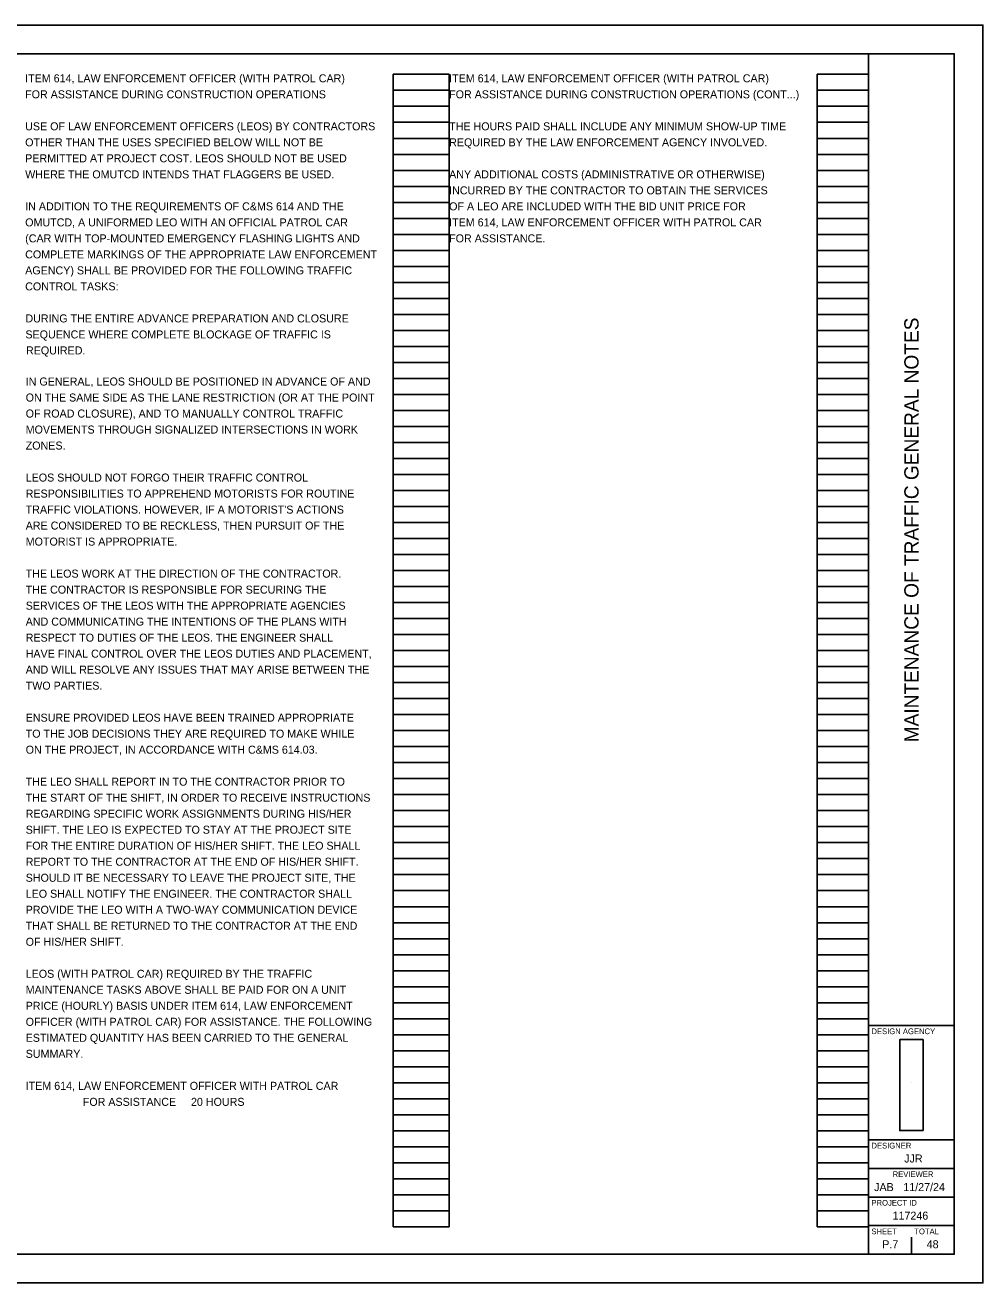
# Model space of a CAD drawing. Extents: x -1.4 to 32.6, y -1 to 21.
# Drawn here: x 15.82 to 32.57, y -0.97 to 21.03 of the extents above; entities that cross this region are included whole.
import ezdxf

# ---------------------------------------------------------------- set-up
doc = ezdxf.new("R2010")
doc.units = 0
for name, color, linetype in [('SH_Border', 7, 'Continuous'), ('SH_Cut_Line', 7, 'Continuous'), ('SH_Data', 7, 'Continuous'), ('SH_Text', 7, 'Continuous')]:
    doc.layers.add(name, color=color, linetype=linetype)

msp = doc.modelspace()

# ---------------------------------------------------------------- linework, layer by layer
at = {"layer": 'SH_Border'}
for p, q in [((30.575, -0.468), (30.575, 20.532)), ((30.575, 3.532), (32.075, 3.532)), ((30.575, 1.532), (32.075, 1.532)), ((30.575, 1.032), (32.075, 1.032)), ((30.575, 0.532), (32.075, 0.532)), ((30.575, 0.032), (32.075, 0.032))]:
    msp.add_line(p, q, dxfattribs=at)
msp.add_lwpolyline([(0.075, 20.532), (32.075, 20.532), (32.075, -0.468), (0.075, -0.468)], close=True, dxfattribs=at)
at = {"layer": 'SH_Cut_Line'}
msp.add_lwpolyline([(-1.425, -0.968), (32.575, -0.968), (32.575, 21.032), (-1.425, 21.032)], close=True, dxfattribs=at)
at = {"layer": 'SH_Data'}
for p, q in [((22.255, 0.012), (22.255, 20.172)), ((22.255, 20.172), (23.235, 20.172)), ((23.235, 0.012), (23.235, 20.172)), ((29.675, 0.012), (29.675, 20.172)), ((29.675, 20.172), (30.575, 20.172)), ((30.575, 0.012), (30.575, 20.172)), ((22.255, 19.892), (23.235, 19.892)), ((29.675, 19.892), (30.575, 19.892)), ((22.255, 19.612), (23.235, 19.612)), ((29.675, 19.612), (30.575, 19.612)), ((22.255, 19.332), (23.235, 19.332)), ((29.675, 19.332), (30.575, 19.332)), ((22.255, 19.052), (23.235, 19.052)), ((29.675, 19.052), (30.575, 19.052)), ((22.255, 18.772), (23.235, 18.772)), ((29.675, 18.772), (30.575, 18.772)), ((22.255, 18.492), (23.235, 18.492)), ((29.675, 18.492), (30.575, 18.492)), ((22.255, 18.212), (23.235, 18.212)), ((29.675, 18.212), (30.575, 18.212)), ((22.255, 17.932), (23.235, 17.932)), ((29.675, 17.932), (30.575, 17.932)), ((22.255, 17.652), (23.235, 17.652)), ((29.675, 17.652), (30.575, 17.652)), ((22.255, 17.372), (23.235, 17.372)), ((29.675, 17.372), (30.575, 17.372)), ((22.255, 17.092), (23.235, 17.092)), ((29.675, 17.092), (30.575, 17.092)), ((22.255, 16.812), (23.235, 16.812)), ((29.675, 16.812), (30.575, 16.812)), ((22.255, 16.532), (23.235, 16.532)), ((29.675, 16.532), (30.575, 16.532)), ((22.255, 16.252), (23.235, 16.252)), ((29.675, 16.252), (30.575, 16.252)), ((22.255, 15.972), (23.235, 15.972)), ((29.675, 15.972), (30.575, 15.972)), ((22.255, 15.692), (23.235, 15.692)), ((29.675, 15.692), (30.575, 15.692)), ((22.255, 15.412), (23.235, 15.412)), ((29.675, 15.412), (30.575, 15.412)), ((22.255, 15.132), (23.235, 15.132)), ((29.675, 15.132), (30.575, 15.132)), ((22.255, 14.852), (23.235, 14.852)), ((29.675, 14.852), (30.575, 14.852)), ((22.255, 14.572), (23.235, 14.572)), ((29.675, 14.572), (30.575, 14.572)), ((22.255, 14.292), (23.235, 14.292)), ((29.675, 14.292), (30.575, 14.292)), ((22.255, 14.012), (23.235, 14.012)), ((29.675, 14.012), (30.575, 14.012)), ((22.255, 13.732), (23.235, 13.732)), ((29.675, 13.732), (30.575, 13.732)), ((22.255, 13.452), (23.235, 13.452)), ((29.675, 13.452), (30.575, 13.452)), ((22.255, 13.172), (23.235, 13.172)), ((29.675, 13.172), (30.575, 13.172)), ((22.255, 12.892), (23.235, 12.892)), ((29.675, 12.892), (30.575, 12.892)), ((22.255, 12.612), (23.235, 12.612)), ((29.675, 12.612), (30.575, 12.612)), ((22.255, 12.332), (23.235, 12.332)), ((29.675, 12.332), (30.575, 12.332)), ((22.255, 12.052), (23.235, 12.052)), ((29.675, 12.052), (30.575, 12.052)), ((22.255, 11.772), (23.235, 11.772)), ((29.675, 11.772), (30.575, 11.772)), ((22.255, 11.492), (23.235, 11.492)), ((29.675, 11.492), (30.575, 11.492)), ((22.255, 11.212), (23.235, 11.212)), ((29.675, 11.212), (30.575, 11.212)), ((22.255, 10.932), (23.235, 10.932)), ((29.675, 10.932), (30.575, 10.932)), ((22.255, 10.652), (23.235, 10.652)), ((29.675, 10.652), (30.575, 10.652)), ((22.255, 10.372), (23.235, 10.372)), ((29.675, 10.372), (30.575, 10.372)), ((22.255, 10.092), (23.235, 10.092)), ((29.675, 10.092), (30.575, 10.092)), ((22.255, 9.812), (23.235, 9.812)), ((29.675, 9.812), (30.575, 9.812)), ((22.255, 9.532), (23.235, 9.532)), ((29.675, 9.532), (30.575, 9.532)), ((22.255, 9.252), (23.235, 9.252)), ((29.675, 9.252), (30.575, 9.252)), ((22.255, 8.972), (23.235, 8.972)), ((29.675, 8.972), (30.575, 8.972)), ((22.255, 8.692), (23.235, 8.692)), ((29.675, 8.692), (30.575, 8.692)), ((22.255, 8.412), (23.235, 8.412)), ((29.675, 8.412), (30.575, 8.412)), ((22.255, 8.132), (23.235, 8.132)), ((29.675, 8.132), (30.575, 8.132)), ((22.255, 7.852), (23.235, 7.852)), ((29.675, 7.852), (30.575, 7.852)), ((22.255, 7.572), (23.235, 7.572)), ((29.675, 7.572), (30.575, 7.572)), ((22.255, 7.292), (23.235, 7.292)), ((29.675, 7.292), (30.575, 7.292)), ((22.255, 7.012), (23.235, 7.012)), ((29.675, 7.012), (30.575, 7.012)), ((22.255, 6.732), (23.235, 6.732)), ((29.675, 6.732), (30.575, 6.732)), ((22.255, 6.452), (23.235, 6.452)), ((29.675, 6.452), (30.575, 6.452)), ((22.255, 6.172), (23.235, 6.172)), ((29.675, 6.172), (30.575, 6.172)), ((22.255, 5.892), (23.235, 5.892)), ((29.675, 5.892), (30.575, 5.892)), ((22.255, 5.612), (23.235, 5.612)), ((29.675, 5.612), (30.575, 5.612)), ((22.255, 5.332), (23.235, 5.332)), ((29.675, 5.332), (30.575, 5.332)), ((22.255, 5.052), (23.235, 5.052)), ((29.675, 5.052), (30.575, 5.052)), ((22.255, 4.772), (23.235, 4.772)), ((29.675, 4.772), (30.575, 4.772)), ((22.255, 4.492), (23.235, 4.492)), ((29.675, 4.492), (30.575, 4.492)), ((22.255, 4.212), (23.235, 4.212)), ((29.675, 4.212), (30.575, 4.212)), ((22.255, 3.932), (23.235, 3.932)), ((29.675, 3.932), (30.575, 3.932)), ((22.255, 3.652), (23.235, 3.652)), ((29.675, 3.652), (30.575, 3.652)), ((22.255, 3.372), (23.235, 3.372)), ((29.675, 3.372), (30.575, 3.372)), ((22.255, 3.092), (23.235, 3.092)), ((29.675, 3.092), (30.575, 3.092)), ((22.255, 2.812), (23.235, 2.812)), ((29.675, 2.812), (30.575, 2.812)), ((22.255, 2.532), (23.235, 2.532)), ((29.675, 2.532), (30.575, 2.532)), ((31.325, 2.532), (31.325, 2.532)), ((22.255, 2.252), (23.235, 2.252)), ((29.675, 2.252), (30.575, 2.252)), ((22.255, 1.972), (23.235, 1.972)), ((29.675, 1.972), (30.575, 1.972)), ((22.255, 1.692), (23.235, 1.692)), ((29.675, 1.692), (30.575, 1.692)), ((22.255, 1.412), (23.235, 1.412)), ((29.675, 1.412), (30.575, 1.412)), ((22.255, 1.132), (23.235, 1.132)), ((29.675, 1.132), (30.575, 1.132)), ((22.255, 0.852), (23.235, 0.852)), ((29.675, 0.852), (30.575, 0.852)), ((22.255, 0.572), (23.235, 0.572)), ((29.675, 0.572), (30.575, 0.572)), ((22.255, 0.292), (23.235, 0.292)), ((29.675, 0.292), (30.575, 0.292)), ((22.255, 0.012), (23.235, 0.012)), ((29.675, 0.012), (30.575, 0.012)), ((31.325, -0.468), (31.325, -0.168)), ((30.95, -0.293), (30.95, -0.293))]:
    msp.add_line(p, q, dxfattribs=at)
at = {"layer": 'SH_Text'}
msp.add_lwpolyline([(31.53, 1.695), (31.53, 3.286), (31.119, 3.286), (31.119, 1.695)], close=True, dxfattribs=at)

# ---------------------------------------------------------------- texts
at = {"layer": 'SH_Data'}
msp.add_text('MAINTENANCE OF TRAFFIC GENERAL NOTES', height=0.25, rotation=90, dxfattribs=at).set_placement((31.45, 8.487))
for s, height, p in [('DESIGN AGENCY', 0.1, (30.625, 3.382)), ('DESIGNER', 0.1, (30.625, 1.382)), ('JJR', 0.14, (31.199, 1.137)), ('REVIEWER', 0.1, (30.996, 0.882)), ('JAB', 0.14, (30.672, 0.637)), ('11/27/24', 0.14, (31.182, 0.637)), ('PROJECT ID', 0.1, (30.625, 0.382)), ('117246', 0.14, (30.994, 0.137)), ('SHEET', 0.1, (30.625, -0.118)), ('TOTAL', 0.1, (31.375, -0.118)), ('P.7', 0.14, (30.814, -0.363)), ('48', 0.14, (31.592, -0.363))]:
    msp.add_text(s, height=height, dxfattribs=at).set_placement(p)
at = {"layer": 'SH_Text'}
for s, p in [('ITEM 614, LAW ENFORCEMENT OFFICER (WITH PATROL CAR)', (15.815, 20.032)), ('ITEM 614, LAW ENFORCEMENT OFFICER (WITH PATROL CAR)', (23.235, 20.032)), ('FOR ASSISTANCE DURING CONSTRUCTION OPERATIONS', (15.815, 19.752)), ('FOR ASSISTANCE DURING CONSTRUCTION OPERATIONS (CONT...)', (23.235, 19.752)), ('USE OF LAW ENFORCEMENT OFFICERS (LEOS) BY CONTRACTORS', (15.816, 19.192)), ('THE HOURS PAID SHALL INCLUDE ANY MINIMUM SHOW-UP TIME', (23.235, 19.192)), ('OTHER THAN THE USES SPECIFIED BELOW WILL NOT BE', (15.816, 18.912)), ('REQUIRED BY THE LAW ENFORCEMENT AGENCY INVOLVED.', (23.235, 18.912)), ('PERMITTED AT PROJECT COST. LEOS SHOULD NOT BE USED', (15.816, 18.632)), ('WHERE THE OMUTCD INTENDS THAT FLAGGERS BE USED.', (15.816, 18.352)), ('ANY ADDITIONAL COSTS (ADMINISTRATIVE OR OTHERWISE)', (23.235, 18.352)), ('INCURRED BY THE CONTRACTOR TO OBTAIN THE SERVICES', (23.235, 18.072)), ('IN ADDITION TO THE REQUIREMENTS OF C&MS 614 AND THE', (15.816, 17.792)), ('OF A LEO ARE INCLUDED WITH THE BID UNIT PRICE FOR', (23.235, 17.792)), ('OMUTCD, A UNIFORMED LEO WITH AN OFFICIAL PATROL CAR', (15.816, 17.512)), ('ITEM 614, LAW ENFORCEMENT OFFICER WITH PATROL CAR', (23.235, 17.512)), ('(CAR WITH TOP-MOUNTED EMERGENCY FLASHING LIGHTS AND', (15.816, 17.232)), ('FOR ASSISTANCE.', (23.235, 17.232)), ('COMPLETE MARKINGS OF THE APPROPRIATE LAW ENFORCEMENT', (15.816, 16.952)), ('AGENCY) SHALL BE PROVIDED FOR THE FOLLOWING TRAFFIC', (15.816, 16.672)), ('CONTROL TASKS:', (15.816, 16.392)), ('    DURING THE ENTIRE ADVANCE PREPARATION AND CLOSURE', (15.612, 15.832)), ('    SEQUENCE WHERE COMPLETE BLOCKAGE OF TRAFFIC IS', (15.612, 15.552)), ('    REQUIRED.', (15.622, 15.272)), ('IN GENERAL, LEOS SHOULD BE POSITIONED IN ADVANCE OF AND', (15.825, 14.728)), ('ON THE SAME SIDE AS THE LANE RESTRICTION (OR AT THE POINT', (15.825, 14.448)), ('OF ROAD CLOSURE), AND TO MANUALLY CONTROL TRAFFIC', (15.825, 14.168)), ('MOVEMENTS THROUGH SIGNALIZED INTERSECTIONS IN WORK', (15.825, 13.888)), ('ZONES.', (15.825, 13.608)), ('LEOS SHOULD NOT FORGO THEIR TRAFFIC CONTROL', (15.825, 13.048)), ('RESPONSIBILITIES TO APPREHEND MOTORISTS FOR ROUTINE', (15.825, 12.768)), ("TRAFFIC VIOLATIONS. HOWEVER, IF A MOTORIST'S ACTIONS", (15.825, 12.488)), ('ARE CONSIDERED TO BE RECKLESS, THEN PURSUIT OF THE', (15.825, 12.208)), ('MOTORIST IS APPROPRIATE.', (15.825, 11.928)), ('THE LEOS WORK AT THE DIRECTION OF THE CONTRACTOR.', (15.825, 11.368)), ('THE CONTRACTOR IS RESPONSIBLE FOR SECURING THE', (15.825, 11.088)), ('SERVICES OF THE LEOS WITH THE APPROPRIATE AGENCIES', (15.825, 10.808)), ('AND COMMUNICATING THE INTENTIONS OF THE PLANS WITH', (15.825, 10.528)), ('RESPECT TO DUTIES OF THE LEOS. THE ENGINEER SHALL', (15.825, 10.248)), ('HAVE FINAL CONTROL OVER THE LEOS DUTIES AND PLACEMENT,', (15.825, 9.968)), ('AND WILL RESOLVE ANY ISSUES THAT MAY ARISE BETWEEN THE', (15.825, 9.688)), ('TWO PARTIES.', (15.825, 9.408)), ('ENSURE PROVIDED LEOS HAVE BEEN TRAINED APPROPRIATE', (15.825, 8.848)), ('TO THE JOB DECISIONS THEY ARE REQUIRED TO MAKE WHILE', (15.825, 8.568)), ('ON THE PROJECT, IN ACCORDANCE WITH C&MS 614.03.', (15.825, 8.288)), ('THE LEO SHALL REPORT IN TO THE CONTRACTOR PRIOR TO', (15.825, 7.728)), ('THE START OF THE SHIFT, IN ORDER TO RECEIVE INSTRUCTIONS', (15.825, 7.448)), ('REGARDING SPECIFIC WORK ASSIGNMENTS DURING HIS/HER', (15.825, 7.168)), ('SHIFT. THE LEO IS EXPECTED TO STAY AT THE PROJECT SITE', (15.825, 6.888)), ('FOR THE ENTIRE DURATION OF HIS/HER SHIFT. THE LEO SHALL', (15.825, 6.608)), ('REPORT TO THE CONTRACTOR AT THE END OF HIS/HER SHIFT.', (15.825, 6.328)), ('SHOULD IT BE NECESSARY TO LEAVE THE PROJECT SITE, THE', (15.825, 6.048)), ('LEO SHALL NOTIFY THE ENGINEER. THE CONTRACTOR SHALL', (15.825, 5.768)), ('PROVIDE THE LEO WITH A TWO-WAY COMMUNICATION DEVICE', (15.825, 5.488)), ('THAT SHALL BE RETURNED TO THE CONTRACTOR AT THE END', (15.825, 5.208)), ('OF HIS/HER SHIFT.', (15.825, 4.928)), ('LEOS (WITH PATROL CAR) REQUIRED BY THE TRAFFIC', (15.825, 4.368)), ('MAINTENANCE TASKS ABOVE SHALL BE PAID FOR ON A UNIT', (15.825, 4.088)), ('PRICE (HOURLY) BASIS UNDER ITEM 614, LAW ENFORCEMENT', (15.825, 3.808)), ('OFFICER (WITH PATROL CAR) FOR ASSISTANCE. THE FOLLOWING', (15.825, 3.528)), ('ESTIMATED QUANTITY HAS BEEN CARRIED TO THE GENERAL', (15.825, 3.248)), ('SUMMARY.', (15.825, 2.968)), ('ITEM 614, LAW ENFORCEMENT OFFICER WITH PATROL CAR', (15.825, 2.408)), ('                         FOR ASSISTANCE     20 HOURS', (15.524, 2.128))]:
    msp.add_text(s, height=0.14, dxfattribs=at).set_placement(p)

doc.saveas('drawing.dxf')
